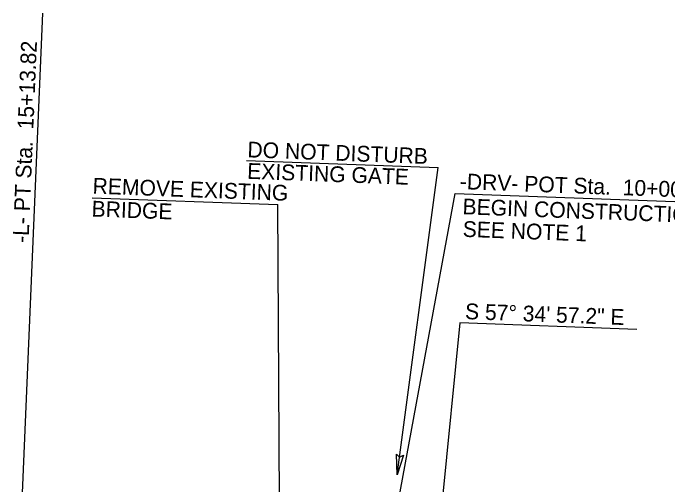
# Model space of a CAD drawing. Extents: x 2170295 to 2171718, y 723585 to 724580.
# Drawn here: x 2170913.1 to 2171203.6, y 724140.1 to 724349.6 of the extents above; entities that cross this region are included whole.
import ezdxf

# ---------------------------------------------------------------- set-up
doc = ezdxf.new("R2010")
doc.units = 0
for name, color, linetype in [('Prop Dimension', 7, 'Continuous'), ('Prop DSN Text', 7, 'Continuous'), ('Prop Horizontal Alignment Direction Label', 7, 'Continuous'), ('Prop Horizontal Alignment Station Label', 7, 'Continuous'), ('Prop Terminator CELL', 7, 'Continuous')]:
    doc.layers.add(name, color=color, linetype=linetype)

msp = doc.modelspace()

# ---------------------------------------------------------------- linework, layer by layer
at = {"layer": 'Prop Dimension'}
for p, q in [((2171016.65, 724284.11), (2171101.66, 724280.93)), ((2171083.56, 724144.53), (2171101.66, 724280.93)), ((2170948.19, 724267.59), (2171030.57, 724264.51)), ((2171031.51, 724075.41), (2171030.57, 724264.51))]:
    msp.add_line(p, q, dxfattribs=at)
at = {"layer": 'Prop Horizontal Alignment Direction Label'}
for p, q in [((2171111.26, 724212.03), (2171100.26, 724100.24)), ((2171189.86, 724209.09), (2171111.26, 724212.03))]:
    msp.add_line(p, q, dxfattribs=at)
at = {"layer": 'Prop Horizontal Alignment Station Label'}
for p, q in [((2170914.68, 724076.31), (2170926.22, 724349.56)), ((2171080.67, 724114.32), (2171109.24, 724269.49)), ((2171109.24, 724269.49), (2171236.27, 724264.74))]:
    msp.add_line(p, q, dxfattribs=at)
at = {"layer": 'Prop Terminator CELL'}
msp.add_lwpolyline([(2171086.28, 724153.25), (2171083.56, 724144.53), (2171083.17, 724153.71), (2171084.6, 724152.36)], close=True, dxfattribs=at)

# ---------------------------------------------------------------- texts
at = {"layer": 'Prop DSN Text'}
for s, p in [('DO NOT DISTURB', (2171016.96, 724285.53)), ('EXISTING GATE', (2171016.85, 724276.01)), ('REMOVE EXISTING', (2170948.25, 724269.43)), ('BRIDGE', (2170947.81, 724259.27))]:
    msp.add_text(s, height=7, rotation=357.8578, dxfattribs=at).set_placement(p)
at = {"layer": 'Prop Horizontal Alignment Direction Label'}
msp.add_text('S 57%%d 34\' 57.2" E', height=7, rotation=357.8574, dxfattribs=at).set_placement((2171113.52, 724213.7))
at = {"layer": 'Prop Horizontal Alignment Station Label'}
for s, rotation, p in [('-L- PT Sta.  15+13.82', 87.5825, (2170919.9, 724247.41)), ('-DRV- POT Sta.  10+00.00', 357.8574, (2171111.21, 724271.42)), ('BEGIN CONSTRUCTION', 357.8574, (2171112.41, 724260.26)), ('SEE NOTE 1', 357.8574, (2171112.48, 724250.25))]:
    msp.add_text(s, height=7, rotation=rotation, dxfattribs=at).set_placement(p)

doc.saveas('drawing.dxf')
